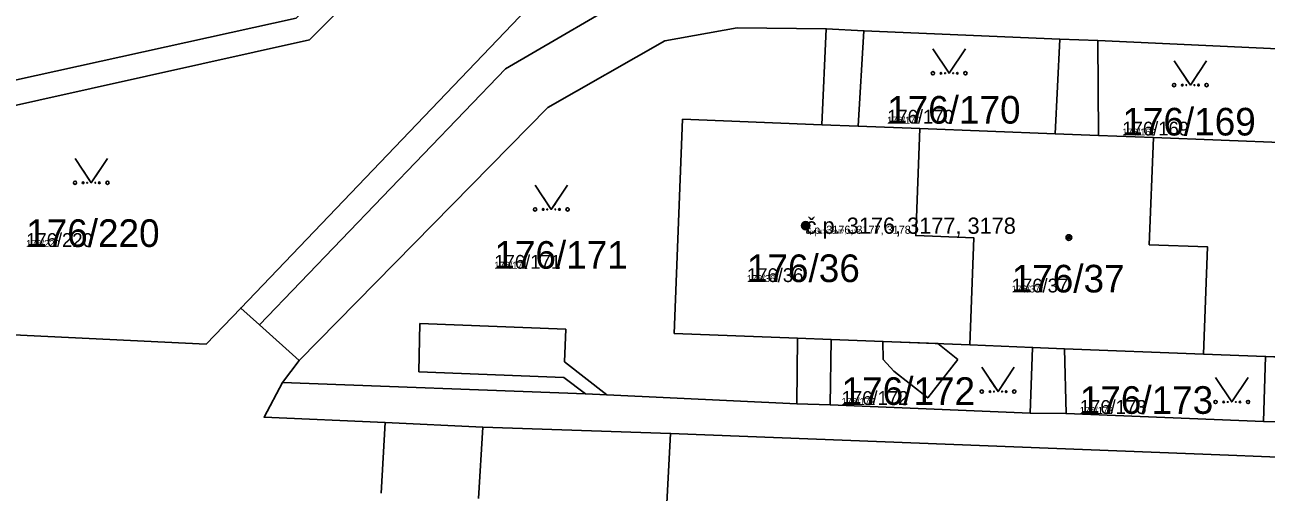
# Model space of a CAD drawing. Extents: x -759873 to -758487, y -975024 to -973516.
# Drawn here: x -759456.7 to -759380.2, y -974864.9 to -974836.2 of the extents above; entities that cross this region are included whole.
import ezdxf

# ---------------------------------------------------------------- set-up
doc = ezdxf.new("R2010")
doc.units = 0
for name, color, linetype in [('KAT_02_hranice parcel', 7, 'Continuous'), ('KAT_03_1000_st čísla parcelní', 7, 'Continuous'), ('KAT_03_1000_čísla parcelní', 7, 'Continuous'), ('KAT_03_1000_čísla popisná', 7, 'Continuous'), ('KAT_03_250_st čísla parcelní', 7, 'Continuous'), ('KAT_03_250_čísla parcelní', 7, 'Continuous'), ('KAT_03_250_čísla popisná', 7, 'Continuous'), ('KAT_03_500_st čísla parcelní', 7, 'Continuous'), ('KAT_03_500_čísla parcelní', 7, 'Continuous'), ('KAT_03_500_čísla popisná', 7, 'Continuous'), ('KAT_04_vnitřní kresba', 7, 'Continuous'), ('KAT_05_1000_značky kultur', 7, 'Continuous'), ('KAT_05_250_značky kultur', 7, 'Continuous'), ('KAT_05_500_značky kultur', 7, 'Continuous'), ('KAT_07_1000_značky budov', 7, 'Continuous'), ('KAT_07_250_značky budov', 7, 'Continuous'), ('KAT_07_500_značky budov', 7, 'Continuous'), ('KAT_10_věcná břemena', 7, 'Continuous'), ('KAT_14_plocha_budovy', 7, 'Continuous'), ('KAT_14_plocha_pozemek', 7, 'Continuous')]:
    doc.layers.add(name, color=color, linetype=linetype)

msp = doc.modelspace()

# ---------------------------------------------------------------- linework, layer by layer
at = {"layer": 'KAT_02_hranice parcel'}
for p, q in [((-759405.01, -974836.55), (-759407.32, -974836.43)), ((-759405.01, -974836.55), (-759392.95, -974837.08)), ((-759390.6, -974837.16), (-759392.95, -974837.08)), ((-759390.6, -974837.16), (-759378.65, -974837.7)), ((-759442.22, -974854.65), (-759443.37, -974853.62)), ((-759439.77, -974856.85), (-759442.22, -974854.65)), ((-759440.79, -974858.2), (-759439.77, -974856.85)), ((-759409.14, -974859.51), (-759407.08, -974859.58)), ((-759407.08, -974859.58), (-759394.77, -974860.08)), ((-759394.77, -974860.08), (-759392.56, -974860.11)), ((-759392.56, -974860.11), (-759380.41, -974860.6)), ((-759380.41, -974860.6), (-759378.32, -974860.64))]:
    msp.add_line(p, q, dxfattribs=at)
for points in [[(-759522.73, -974853.07), (-759508.22, -974850.21), (-759486.35, -974846.03), (-759478.35, -974845.69), (-759475.89, -974845.29), (-759439.14, -974837.12), (-759426.25, -974824.24), (-759419.13, -974816.38), (-759413.01, -974806.77), (-759411.92, -974804.78)], [(-759434.61, -974814.81), (-759420.32, -974815.53), (-759427.43, -974823.31), (-759439.96, -974835.78), (-759476.18, -974843.76), (-759458.03, -974819.25), (-759456.41, -974817.02)], [(-759443.37, -974853.62), (-759424.85, -974834.26), (-759422.46, -974832.5), (-759419.67, -974831.59), (-759416.69, -974831.27), (-759413.9, -974831.28), (-759382.67, -974832.32)], [(-759281.55, -974837.72), (-759288.97, -974837.7), (-759308.21, -974836.87), (-759325.02, -974836.15), (-759358.04, -974834.77), (-759390.43, -974833.42), (-759411.31, -974832.59), (-759418.48, -974833.88), (-759427.06, -974838.9), (-759442.22, -974854.65)], [(-759439.77, -974856.85), (-759424.46, -974841.28), (-759417.27, -974837.18), (-759412.8, -974836.38), (-759407.32, -974836.43)], [(-759407.32, -974836.43), (-759407.59, -974842.34), (-759416.17, -974842), (-759416.68, -974855.18), (-759409.09, -974855.48), (-759409.14, -974859.51)], [(-759401.56, -974842.57), (-759405.36, -974842.42), (-759405.01, -974836.55)], [(-759392.95, -974837.08), (-759393.24, -974842.9), (-759401.56, -974842.57)], [(-759387.18, -974843.13), (-759390.57, -974843), (-759390.6, -974837.16)], [(-759378.65, -974837.7), (-759378.84, -974843.46), (-759387.18, -974843.13)], [(-759398.48, -974855.89), (-759398.23, -974849.3), (-759401.82, -974849.16), (-759401.56, -974842.57)], [(-759384.11, -974856.45), (-759383.85, -974849.86), (-759387.44, -974849.72), (-759387.18, -974843.13)], [(-759443.37, -974853.62), (-759445.5, -974855.85), (-759459.93, -974855.14), (-759460.02, -974857.37), (-759508.63, -974855.12), (-759522.81, -974859.11)], [(-759407.08, -974859.58), (-759407.03, -974855.56), (-759398.48, -974855.89)], [(-759398.48, -974855.89), (-759394.62, -974856.04), (-759394.77, -974860.08)], [(-759392.56, -974860.11), (-759392.65, -974856.12), (-759384.11, -974856.45)], [(-759384.11, -974856.45), (-759380.28, -974856.6), (-759380.41, -974860.6)], [(-759434.72, -974865.02), (-759434.47, -974860.67), (-759441.93, -974860.34), (-759440.79, -974858.2)], [(-759440.79, -974858.2), (-759422.15, -974858.9), (-759420.83, -974858.95), (-759409.14, -974859.51)], [(-759417.43, -974871.08), (-759416.91, -974861.33), (-759428.46, -974860.94), (-759428.73, -974865.34)]]:
    msp.add_lwpolyline(points, dxfattribs=at)
at = {"layer": 'KAT_03_1000_čísla popisná'}
msp.add_circle((-759408.59, -974848.55), 0.25, dxfattribs=at)
at = {"layer": 'KAT_03_250_čísla popisná'}
msp.add_circle((-759408.59, -974848.55), 0.0625, dxfattribs=at)
at = {"layer": 'KAT_03_500_čísla popisná'}
msp.add_circle((-759408.59, -974848.55), 0.125, dxfattribs=at)
at = {"layer": 'KAT_04_vnitřní kresba'}
for p, q in [((-759407.59, -974842.34), (-759405.36, -974842.42)), ((-759393.24, -974842.9), (-759390.57, -974843)), ((-759432.4, -974857.54), (-759432.35, -974854.57)), ((-759432.35, -974854.57), (-759423.36, -974854.92)), ((-759423.44, -974856.92), (-759423.36, -974854.92)), ((-759409.09, -974855.48), (-759407.03, -974855.56)), ((-759394.62, -974856.04), (-759392.65, -974856.12)), ((-759423.44, -974856.92), (-759420.83, -974858.95)), ((-759380.28, -974856.6), (-759378.22, -974856.68)), ((-759432.4, -974857.54), (-759423.48, -974857.89)), ((-759423.48, -974857.89), (-759422.15, -974858.9)), ((-759434.47, -974860.67), (-759428.46, -974860.94)), ((-759416.91, -974861.33), (-759382.57, -974862.68)), ((-759382.57, -974862.68), (-759352.26, -974863.8))]:
    msp.add_line(p, q, dxfattribs=at)
at = {"layer": 'KAT_05_1000_značky kultur'}
for points in [[(-759400.76, -974837.669), (-759399.76, -974839.17), (-759398.76, -974837.669)], [(-759385.91, -974838.399), (-759384.91, -974839.9), (-759383.91, -974838.399)], [(-759453.57, -974844.409), (-759452.57, -974845.91), (-759451.57, -974844.409)], [(-759425.25, -974846.049), (-759424.25, -974847.55), (-759423.25, -974846.049)], [(-759397.75, -974857.259), (-759396.75, -974858.76), (-759395.75, -974857.259)], [(-759383.36, -974857.899), (-759382.36, -974859.4), (-759381.36, -974857.899)]]:
    msp.add_lwpolyline(points, dxfattribs=at)
for centre in [(-759400.76, -974839.169), (-759398.76, -974839.169), (-759385.91, -974839.899), (-759383.91, -974839.899), (-759453.57, -974845.909), (-759451.57, -974845.909), (-759425.25, -974847.549), (-759423.25, -974847.549), (-759397.75, -974858.759), (-759395.75, -974858.759), (-759383.36, -974859.399), (-759381.36, -974859.399)]:
    msp.add_circle(centre, 0.1, dxfattribs=at)
at = {"layer": 'KAT_05_250_značky kultur'}
for points in [[(-759400.01, -974838.795), (-759399.76, -974839.17), (-759399.51, -974838.795)], [(-759385.16, -974839.525), (-759384.91, -974839.9), (-759384.66, -974839.525)], [(-759452.82, -974845.535), (-759452.57, -974845.91), (-759452.32, -974845.535)], [(-759424.5, -974847.175), (-759424.25, -974847.55), (-759424, -974847.175)], [(-759397, -974858.385), (-759396.75, -974858.76), (-759396.5, -974858.385)], [(-759382.61, -974859.025), (-759382.36, -974859.4), (-759382.11, -974859.025)]]:
    msp.add_lwpolyline(points, dxfattribs=at)
for centre in [(-759400.01, -974839.17), (-759399.51, -974839.17), (-759385.16, -974839.9), (-759384.66, -974839.9), (-759452.82, -974845.91), (-759452.32, -974845.91), (-759424.5, -974847.55), (-759424, -974847.55), (-759397, -974858.76), (-759396.5, -974858.76), (-759382.61, -974859.4), (-759382.11, -974859.4)]:
    msp.add_circle(centre, 0.025, dxfattribs=at)
at = {"layer": 'KAT_05_500_značky kultur'}
for points in [[(-759400.26, -974838.42), (-759399.76, -974839.17), (-759399.26, -974838.42)], [(-759385.41, -974839.15), (-759384.91, -974839.9), (-759384.41, -974839.15)], [(-759453.07, -974845.16), (-759452.57, -974845.91), (-759452.07, -974845.16)], [(-759424.75, -974846.799), (-759424.25, -974847.55), (-759423.75, -974846.799)], [(-759397.25, -974858.01), (-759396.75, -974858.76), (-759396.25, -974858.01)], [(-759382.86, -974858.65), (-759382.36, -974859.4), (-759381.86, -974858.65)]]:
    msp.add_lwpolyline(points, dxfattribs=at)
for centre in [(-759400.26, -974839.17), (-759399.26, -974839.17), (-759385.41, -974839.9), (-759384.41, -974839.9), (-759453.07, -974845.91), (-759452.07, -974845.91), (-759424.75, -974847.55), (-759423.75, -974847.55), (-759397.25, -974858.76), (-759396.25, -974858.76), (-759382.86, -974859.4), (-759381.86, -974859.4)]:
    msp.add_circle(centre, 0.05, dxfattribs=at)
at = {"layer": 'KAT_07_1000_značky budov'}
for centre in [(-759408.597, -974848.549), (-759392.387, -974849.279)]:
    msp.add_circle(centre, 0.175, dxfattribs=at)
at = {"layer": 'KAT_07_250_značky budov'}
for centre in [(-759408.592, -974848.55), (-759392.382, -974849.28)]:
    msp.add_circle(centre, 0.0437, dxfattribs=at)
at = {"layer": 'KAT_07_500_značky budov'}
for centre in [(-759408.593, -974848.55), (-759392.383, -974849.28)]:
    msp.add_circle(centre, 0.0875, dxfattribs=at)
at = {"layer": 'KAT_10_věcná břemena'}
msp.add_lwpolyline([(-759399.22, -974856.79), (-759400.46, -974855.81), (-759403.85, -974855.68), (-759403.83, -974856.78), (-759403.17, -974857.5), (-759401.08, -974859.15)], close=True, dxfattribs=at)
at = {"layer": 'KAT_14_plocha_budovy'}
msp.add_lwpolyline([(-759369.6, -974857.02), (-759369.08, -974843.84), (-759376.59, -974843.55), (-759378.84, -974843.46), (-759387.18, -974843.13), (-759390.57, -974843), (-759393.24, -974842.9), (-759401.56, -974842.57), (-759405.36, -974842.42), (-759407.59, -974842.34), (-759416.17, -974842), (-759416.68, -974855.18), (-759409.09, -974855.48), (-759407.03, -974855.56), (-759398.48, -974855.89), (-759394.62, -974856.04), (-759392.65, -974856.12), (-759384.11, -974856.45), (-759380.28, -974856.6), (-759378.22, -974856.68)], close=True, dxfattribs=at)
at = {"layer": 'KAT_14_plocha_pozemek'}
for points in [[(-759374.6, -974783.16), (-759387.42, -974782.97), (-759387.48, -974784.74), (-759387.54, -974786.34), (-759387.99, -974786.32), (-759388.88, -974803.28), (-759390.44, -974803.28), (-759393.69, -974803.28), (-759394.17, -974815.54), (-759395.97, -974815.47), (-759396.25, -974822.71), (-759408.59, -974822.23), (-759407.83, -974803.1), (-759411.01, -974802.96), (-759411.07, -974803.92), (-759411.92, -974804.78), (-759413.01, -974806.77), (-759419.13, -974816.38), (-759426.25, -974824.24), (-759439.14, -974837.12), (-759475.89, -974845.29)], [(-759459.93, -974855.14), (-759445.5, -974855.85), (-759443.37, -974853.62), (-759424.85, -974834.26), (-759422.46, -974832.5), (-759419.67, -974831.59), (-759416.69, -974831.27), (-759413.9, -974831.28), (-759382.67, -974832.32), (-759382.66, -974831.98), (-759382.28, -974822.37), (-759381.65, -974805.61), (-759380.83, -974785.21), (-759360.2, -974785.81)], [(-759475.89, -974845.29), (-759439.14, -974837.12), (-759426.25, -974824.24), (-759419.13, -974816.38), (-759413.01, -974806.77), (-759411.92, -974804.78), (-759413.3, -974803.92), (-759414.25, -974806.06), (-759419.38, -974814), (-759434.58, -974813.37), (-759434.61, -974814.81), (-759420.32, -974815.53), (-759427.43, -974823.31), (-759439.96, -974835.78), (-759476.18, -974843.76)], [(-759286.08, -974836), (-759358.04, -974833.14), (-759382.67, -974832.32), (-759413.9, -974831.28), (-759416.69, -974831.27), (-759419.67, -974831.59), (-759422.46, -974832.5), (-759424.85, -974834.26), (-759443.37, -974853.62), (-759442.22, -974854.65), (-759427.06, -974838.9), (-759418.48, -974833.88), (-759411.31, -974832.59), (-759390.43, -974833.42), (-759358.04, -974834.77), (-759325.02, -974836.15), (-759308.21, -974836.87), (-759288.97, -974837.7)], [(-759358.04, -974834.77), (-759390.43, -974833.42), (-759411.31, -974832.59), (-759418.48, -974833.88), (-759427.06, -974838.9), (-759442.22, -974854.65), (-759439.77, -974856.85), (-759424.46, -974841.28), (-759417.27, -974837.18), (-759412.8, -974836.38), (-759407.32, -974836.43), (-759405.01, -974836.55), (-759392.95, -974837.08), (-759390.6, -974837.16), (-759378.65, -974837.7)], [(-759434.72, -974865.02), (-759434.47, -974860.67), (-759441.93, -974860.34), (-759440.79, -974858.2), (-759439.77, -974856.85), (-759442.22, -974854.65), (-759443.37, -974853.62), (-759445.5, -974855.85), (-759459.93, -974855.14)], [(-759378.32, -974860.64), (-759380.41, -974860.6), (-759392.56, -974860.11), (-759394.77, -974860.08), (-759407.08, -974859.58), (-759409.14, -974859.51), (-759420.83, -974858.95), (-759422.15, -974858.9), (-759440.79, -974858.2), (-759441.93, -974860.34), (-759434.47, -974860.67), (-759434.72, -974865.02)], [(-759417.43, -974871.08), (-759416.91, -974861.33), (-759428.46, -974860.94), (-759428.73, -974865.34)], [(-759428.73, -974865.34), (-759428.46, -974860.94), (-759416.91, -974861.33), (-759417.43, -974871.08)]]:
    msp.add_lwpolyline(points, dxfattribs=at)
for points in [[(-759434.61, -974814.81), (-759438.02, -974815.13), (-759438.52, -974827.35), (-759440.32, -974827.27), (-759440.62, -974834.53), (-759452.98, -974834.03), (-759452.24, -974814.85), (-759455.74, -974814.72), (-759456.41, -974817.02), (-759458.03, -974819.25), (-759476.18, -974843.76), (-759439.96, -974835.78), (-759427.43, -974823.31), (-759420.32, -974815.53)], [(-759422.15, -974858.9), (-759420.83, -974858.95), (-759409.14, -974859.51), (-759409.09, -974855.48), (-759416.68, -974855.18), (-759416.17, -974842), (-759407.59, -974842.34), (-759407.32, -974836.43), (-759412.8, -974836.38), (-759417.27, -974837.18), (-759424.46, -974841.28), (-759439.77, -974856.85), (-759440.79, -974858.2)], [(-759416.17, -974842), (-759416.68, -974855.18), (-759409.09, -974855.48), (-759409.14, -974859.51), (-759407.08, -974859.58), (-759407.03, -974855.56), (-759398.48, -974855.89), (-759398.23, -974849.3), (-759401.82, -974849.16), (-759401.56, -974842.57), (-759405.36, -974842.42), (-759405.01, -974836.55), (-759407.32, -974836.43), (-759407.59, -974842.34)], [(-759405.01, -974836.55), (-759405.36, -974842.42), (-759401.56, -974842.57), (-759393.24, -974842.9), (-759392.95, -974837.08)], [(-759394.62, -974856.04), (-759394.77, -974860.08), (-759392.56, -974860.11), (-759392.65, -974856.12), (-759384.11, -974856.45), (-759383.85, -974849.86), (-759387.44, -974849.72), (-759387.18, -974843.13), (-759390.57, -974843), (-759390.6, -974837.16), (-759392.95, -974837.08), (-759393.24, -974842.9), (-759401.56, -974842.57), (-759401.82, -974849.16), (-759398.23, -974849.3), (-759398.48, -974855.89)], [(-759390.6, -974837.16), (-759390.57, -974843), (-759387.18, -974843.13), (-759378.84, -974843.46), (-759378.65, -974837.7)], [(-759376.31, -974837.75), (-759378.65, -974837.7), (-759378.84, -974843.46), (-759387.18, -974843.13), (-759387.44, -974849.72), (-759383.85, -974849.86), (-759384.11, -974856.45), (-759380.28, -974856.6), (-759380.41, -974860.6), (-759378.32, -974860.64), (-759378.22, -974856.68), (-759369.6, -974857.02), (-759369.08, -974843.84), (-759376.59, -974843.55)], [(-759394.77, -974860.08), (-759394.62, -974856.04), (-759398.48, -974855.89), (-759407.03, -974855.56), (-759407.08, -974859.58)], [(-759380.41, -974860.6), (-759380.28, -974856.6), (-759384.11, -974856.45), (-759392.65, -974856.12), (-759392.56, -974860.11)]]:
    msp.add_lwpolyline(points, close=True, dxfattribs=at)

# ---------------------------------------------------------------- texts
at = {"layer": 'KAT_03_1000_st čísla parcelní'}
for s, p in [('176/36', (-759412.21, -974852.02)), ('176/37', (-759395.91, -974852.66))]:
    msp.add_text(s, height=1.7, dxfattribs=at).set_placement(p)
at = {"layer": 'KAT_03_1000_čísla parcelní'}
for s, p in [('176/170', (-759403.58, -974842.27)), ('176/169', (-759389.1, -974843)), ('176/220', (-759456.58, -974849.86)), ('176/171', (-759427.76, -974851.2)), ('176/172', (-759406.38, -974859.58)), ('176/173', (-759391.72, -974860.13))]:
    msp.add_text(s, height=1.7, dxfattribs=at).set_placement(p)
at = {"layer": 'KAT_03_1000_čísla popisná'}
msp.add_text('č.p. 3176, 3177, 3178', height=1, dxfattribs=at).set_placement((-759408.59, -974849.05))
at = {"layer": 'KAT_03_250_st čísla parcelní'}
for s, p in [('176/36', (-759412.21, -974852.02)), ('176/37', (-759395.91, -974852.66))]:
    msp.add_text(s, height=0.425, dxfattribs=at).set_placement(p)
at = {"layer": 'KAT_03_250_čísla parcelní'}
for s, p in [('176/170', (-759403.58, -974842.27)), ('176/169', (-759389.1, -974843)), ('176/220', (-759456.58, -974849.86)), ('176/171', (-759427.76, -974851.2)), ('176/172', (-759406.38, -974859.58)), ('176/173', (-759391.72, -974860.13))]:
    msp.add_text(s, height=0.425, dxfattribs=at).set_placement(p)
at = {"layer": 'KAT_03_250_čísla popisná'}
msp.add_text('č.p. 3176, 3177, 3178', height=0.25, dxfattribs=at).set_placement((-759408.59, -974849.05))
at = {"layer": 'KAT_03_500_st čísla parcelní'}
for s, p in [('176/36', (-759412.21, -974852.02)), ('176/37', (-759395.91, -974852.66))]:
    msp.add_text(s, height=0.85, dxfattribs=at).set_placement(p)
at = {"layer": 'KAT_03_500_čísla parcelní'}
for s, p in [('176/170', (-759403.58, -974842.27)), ('176/169', (-759389.1, -974843)), ('176/220', (-759456.58, -974849.86)), ('176/171', (-759427.76, -974851.2)), ('176/172', (-759406.38, -974859.58)), ('176/173', (-759391.72, -974860.13))]:
    msp.add_text(s, height=0.85, dxfattribs=at).set_placement(p)
at = {"layer": 'KAT_03_500_čísla popisná'}
msp.add_text('č.p. 3176, 3177, 3178', height=0.5, dxfattribs=at).set_placement((-759408.59, -974849.05))

doc.saveas('drawing.dxf')
